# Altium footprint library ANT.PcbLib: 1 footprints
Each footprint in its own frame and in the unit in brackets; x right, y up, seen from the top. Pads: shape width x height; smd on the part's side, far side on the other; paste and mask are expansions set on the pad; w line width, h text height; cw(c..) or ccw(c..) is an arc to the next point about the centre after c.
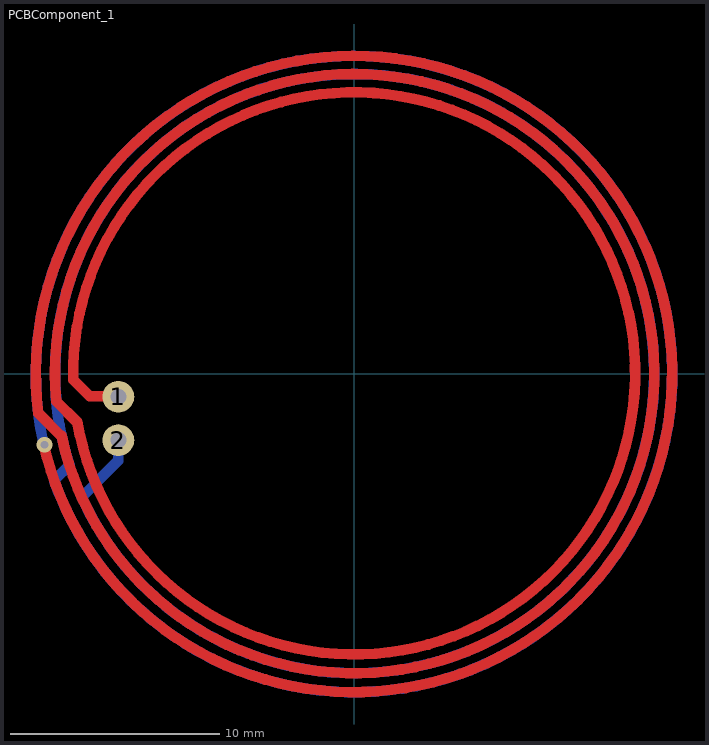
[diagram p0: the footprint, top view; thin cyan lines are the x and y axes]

## PCBComponent_1 [mil]
pads (2):
  round 60 hole 30: 1(-445,-43.17) 2(-445,-125)
via -584.28,-133.72 diameter 30 hole 15
Top Layer:
  lines w15: -460.26,-42.5 -452.3,-50.46
  lines w20: -596.14,-74.45 cw(c-0.75,-0.24) -586.28,-131.22 ; -595.62,-74.38 -552.64,-117.36 ; -562.45,-51.55 -523.17,-90.83 ; -562.13,-51.23 cw(c0.5,0.5) -552.1,-117.24 ; -530.41,-11.29 cw(c-0.55,0.93) -522.57,-90.73 ; -530.21,-11.29 -499,-42.5 -460.26,-42.5
Bottom Layer:
  lines w20: -587.16,-127.22 cw(c-0.74,-0.28) -566.17,-201 ; -565.92,-200.92 -537,-172 ; -537.48,-172.15 cw(c0.49,0.54) -514.14,-232.66 -445,-163.52 -445,-125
